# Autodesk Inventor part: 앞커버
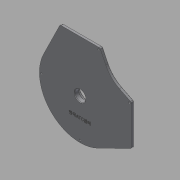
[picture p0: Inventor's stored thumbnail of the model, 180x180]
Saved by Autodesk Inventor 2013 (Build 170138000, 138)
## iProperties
Created: 2017-05
Part Number: 앞커버
Material: 일반
Document SubType Name: Modeling
Designer: mduedu
Density: 1 g/cm^3
Mass: 118.682 g
Surface Area: 500.043 cm^2
Volume: 118.682 cm^3
Author: mduedu
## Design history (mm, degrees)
sketch "스케치1"
  geometry: L1 (-71.801, 35.28)-(-40, 100); L2 (-40, 100)-(40, 100); L3 (40, 100)-(52.248, 75.073); L4 (35.28, 71.801)-(59.768, 59.768); L5 (100, 40)-(100, -40); L6 (100, -40)-(35.28, -71.801); L7 (75.073, 52.248)-(100, 40); L8 (59.768, 59.768)-(71.801, 35.28); L9 (33.075, -67.313)-(95, -36.886); L10 (95, -36.886)-(95, 36.886); L11 (95, 36.886)-(72.868, 47.76); L12 (47.76, 72.868)-(36.886, 95); L13 (36.886, 95)-(-36.886, 95); L14 (-36.886, 95)-(-67.313, 33.075); A1 r 80 centre (0, 0) between (71.801, 35.28) and (-71.801, 35.28); A2 r 80 centre (0, 0) between (35.28, -71.801) and (71.801, 35.28); A3 r 80 centre (0, 0) between (-71.801, 35.28) and (35.28, -71.801); A4 r 50 centre (97.123, 97.123) between (52.248, 75.073) and (75.073, 52.248); A5 r 55 centre (97.123, 97.123) between (47.76, 72.868) and (72.868, 47.76); A6 r 75 centre (0, 0) between (-67.313, 33.075) and (33.075, -67.313); 3 further points
  constraints: 29 end point, 15 tangent, 14 point on circle, 6 centre point, 2 midpoint, 2 perpendicular, 2 point on line, 1 coincident, 1 horizontal, 1 horizontal alignment, 1 vertical alignment, 6 other
  dimensions: "d0" = 160 diameter of A1; "d1" = 100 distance from line of L2 point (0, 0); "d2" = 100 distance from line of L5 point (0, 0); "d3" = 80 distance of L1.end L2.end; "d4" = 80 distance of L5.start L5.end; "d5" = 50 radius of A4; "d6" = 5 distance between parallel lines of L13 L2
extrude "돌출1" new body sketch "스케치1" distance "d7" = 5; taper "d8" = 0 deg
fillet "모깎기1" dims "d9" = 3
sketch "스케치2"
  geometry: C1 r 22 at (0, 0); 1 further point
  constraints: 1 centre point, 1 coincident
  dimensions: "d10" = 44 diameter of C1
extrude "돌출2" join sketch "스케치2" distance "d11" = 12.5; taper "d12" = 0 deg
sketch "스케치3"
  geometry: C1 r 18.5 at (0, 0); 1 further point
  constraints: 1 centre point, 1 coincident
  dimensions: "d13" = 37 diameter of C1
extrude "돌출3" cut sketch "스케치3" distance "d14" = 9; taper "d15" = 0 deg
hole "구멍1" diameter "d18" = 20; stored, may be unused: countersink angle "d22" = 90 deg, drill point angle "d24" = 118 deg; dims "d16" = 10, "d17" = 10, "d19" = 6, "d20" = 4, "d21" = 2, "d23" = 8
fillet "모깎기2" dims "d25" = 3
chamfer "모따기1" distance "d27" = 1; stored, may be unused: second distance "d28" = 2, angle "d29" = 45 deg
sketch "스케치4"
  geometry: 2 further points
  constraints: 1 vertical alignment, 1 other
  dimensions: "d30" = 35 distance of point (0, -35) point (0, 0)
feature "엠보싱1" sketch "스케치4" dims "d31" = 0.5, "d32" = 0
chamfer "모따기2" distance "d33" = 1; stored, may be unused: second distance "d34" = 2, angle "d35" = 45 deg
chamfer "모따기3" distance "d36" = 1; stored, may be unused: second distance "d37" = 2, angle "d38" = 45 deg
sketch "스케치5"
  geometry: L1 (18.989, -35.003)-(17.659, -35.003) reference; L2 (17.659, -35.003)-(17.659, -34.623) reference; L3 (17.659, -34.623)-(18.989, -34.623) reference; L4 (18.989, -34.623)-(18.989, -32.045) reference; L5 (18.989, -32.045)-(19.315, -32.045) reference; L6 (19.45, -32.31)-(19.45, -37.982) reference; L7 (19.45, -37.982)-(18.989, -37.982) reference; L8 (18.989, -37.982)-(18.989, -35.003) reference; L9 (-13.942, -34.352)-(-13.942, -34.746) reference; L10 (-13.942, -34.746)-(-15.061, -34.746) reference; L11 (-15.061, -34.746)-(-15.061, -36.489) reference; L12 (-15.061, -36.489)-(-15.536, -36.489) reference; L13 (-15.536, -36.489)-(-15.536, -31.998) reference; L14 (-15.536, -31.998)-(-15.231, -31.998) reference; L15 (-15.061, -32.263)-(-15.061, -34.352) reference; L16 (-15.061, -34.352)-(-13.942, -34.352) reference; L17 (-14.844, -37.439)-(-14.844, -37.819) reference; L18 (-14.844, -37.819)-(-19.193, -37.819) reference; L19 (-19.193, -37.819)-(-19.193, -36.191) reference; L20 (-19.193, -36.191)-(-18.84, -36.191) reference; L21 (-18.731, -36.408)-(-18.731, -37.439) reference; L22 (-18.731, -37.439)-(-14.844, -37.439) reference; L23 (-17.374, -32.575)-(-18.853, -32.575) reference; L24 (-18.853, -32.575)-(-18.853, -32.222) reference; L25 (-18.853, -32.222)-(-17.374, -32.222) reference; L26 (-17.374, -32.222)-(-17.374, -32.575) reference; L27 (-20.047, -33.382)-(-20.047, -33.029) reference; L28 (-20.047, -33.029)-(-16.282, -33.029) reference; L29 (-16.282, -33.029)-(-16.282, -33.382) reference; L30 (-16.282, -33.382)-(-20.047, -33.382) reference; L31 (-2.917, -37.615)-(-3.474, -36.089) reference; L32 (-3.474, -36.089)-(-5.726, -36.089) reference; L33 (-5.726, -36.089)-(-6.296, -37.615) reference; L34 (-6.296, -37.615)-(-6.777, -37.615) reference; L35 (-6.777, -37.615)-(-4.878, -32.615) reference; L36 (-4.878, -32.615)-(-4.335, -32.615) reference; L37 (-4.335, -32.615)-(-2.436, -37.615) reference; L38 (-2.436, -37.615)-(-2.917, -37.615) reference; L39 (-4.613, -33.104)-(-5.57, -35.675) reference; L40 (-5.57, -35.675)-(-3.636, -35.675) reference; L41 (-3.636, -35.675)-(-4.613, -33.104) reference; L42 (-10.095, -35.851)-(-8.284, -35.851) reference; L43 (-8.284, -35.851)-(-8.284, -37.975) reference; L44 (-8.284, -37.975)-(-8.745, -37.975) reference; L45 (-8.745, -37.975)-(-8.745, -36.225) reference; L46 (-8.745, -36.225)-(-12.578, -36.225) reference; L47 (-12.578, -36.225)-(-12.578, -35.851) reference; L48 (-12.578, -35.851)-(-10.55, -35.851) reference; L49 (-10.55, -35.851)-(-10.55, -34.63) reference; L50 (-10.55, -34.63)-(-13.311, -34.63) reference; L51 (-13.311, -34.63)-(-13.311, -34.257) reference; L52 (-13.311, -34.257)-(-8.942, -34.257) reference; L53 (-8.657, -32.588)-(-12.463, -32.588) reference; L54 (-12.463, -32.588)-(-12.463, -32.208) reference; L55 (-12.463, -32.208)-(-8.175, -32.208) reference; L56 (-8.446, -34.257)-(-7.307, -34.257) reference; L57 (-7.307, -34.257)-(-7.307, -34.63) reference; L58 (-7.307, -34.63)-(-10.095, -34.63) reference; L59 (-10.095, -34.63)-(-10.095, -35.851) reference; L60 (1.526, -32.615)-(1.526, -33.029) reference; L61 (1.526, -33.029)-(-0.034, -33.029) reference; L62 (-0.034, -33.029)-(-0.034, -37.615) reference; L63 (-0.034, -37.615)-(-0.488, -37.615) reference; L64 (-0.488, -37.615)-(-0.488, -33.029) reference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; C1 r 11 at (0, 0) reference; C2 r 4 at (-71, 0); C3 r 4 at (0, -71); C4 r 4 at (91, 34.394); C5 r 4 at (34.394, 91); A1 r 75 centre (0, 0) between (-67.313, 33.075) and (33.075, -67.313) reference; A2 r 3 centre (-35.017, 92) between (-35.017, 95) and (-37.71, 93.323) reference; A3 r 3 centre (35.017, 92) between (37.71, 93.323) and (35.017, 95) reference; A4 r 55 centre (97.123, 97.123) between (47.76, 72.868) and (72.868, 47.76) reference; A5 r 3 centre (92, 35.017) between (95, 35.017) and (93.323, 37.71) reference; A6 r 3 centre (92, -35.017) between (93.323, -37.71) and (95, -35.017) reference; A7 r 75 centre (0, 0) between (-67.313, 33.075) and (33.075, -67.313) reference; 66 further points
  constraints: 6 tangent, 4 centre point, 4 coincident, 3 equal radius, 1 horizontal alignment, 1 vertical alignment, 76 other
  dimensions: "d39" = 8 diameter of C2
  node "절단 모서리 투영1"
sketch "스케치6"
  geometry: 4 further points
  constraints: 4 other
hole "구멍2" sketch "스케치6" at (0, -71), (91, 34.394), (34.394, 91), (-71, 0) diameter "d40" = 3.4; stored, may be unused: countersink angle "d44" = 90 deg, drill point angle "d46" = 0 deg; dims "d41" = 6, "d42" = 4, "d43" = 2, "d45" = 8
node "솔리드1"
